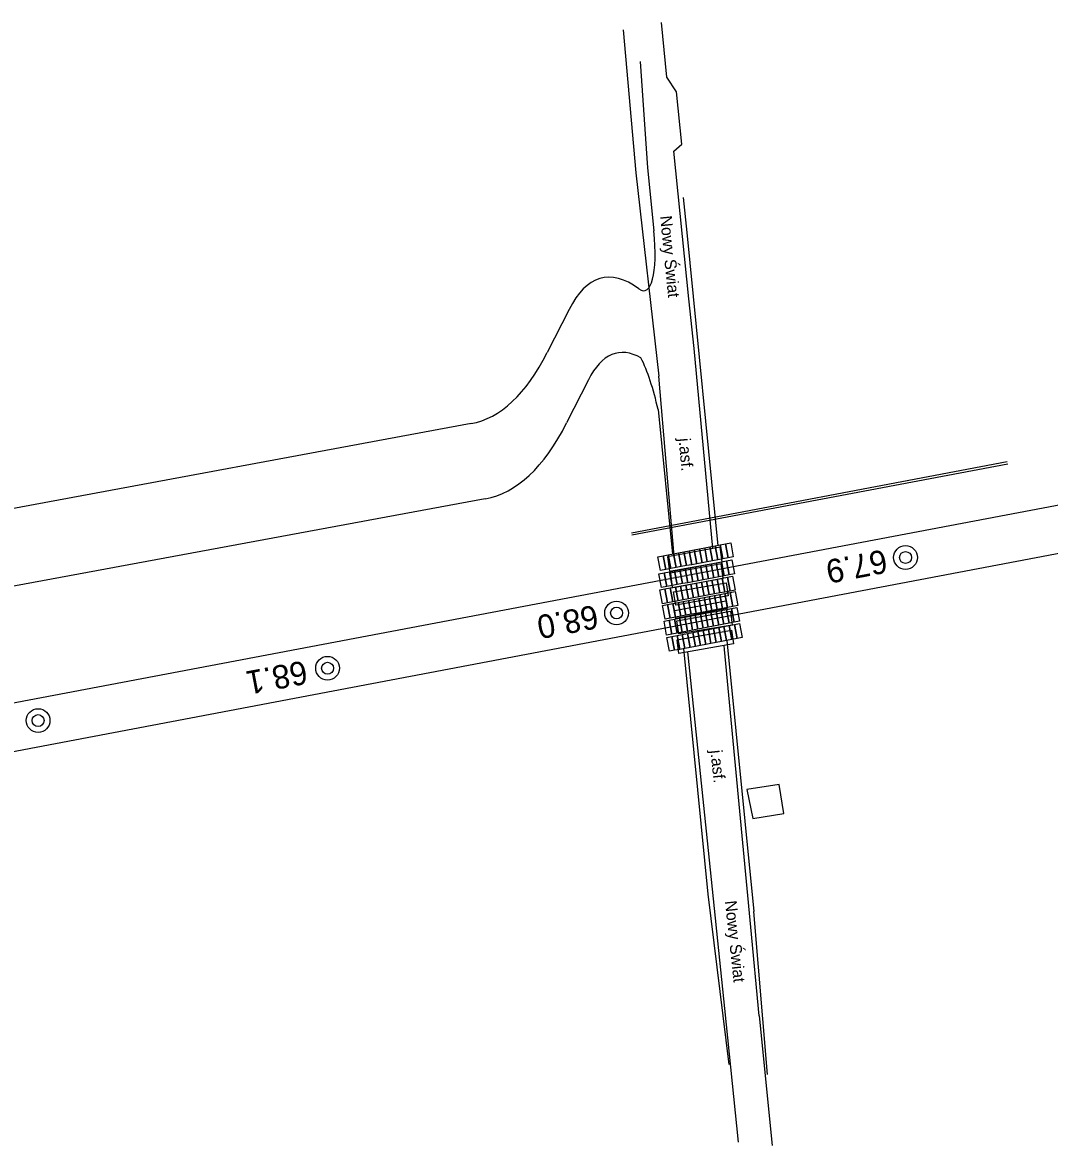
# Model space of a CAD drawing. Extents: x 6541740 to 6566395, y 5525066 to 5530361.
# Drawn here: x 6555554.3 to 6555641.5, y 5525816.3 to 5525911.7 of the extents above; entities that cross this region are included whole.
import ezdxf

# ---------------------------------------------------------------- set-up
doc = ezdxf.new("R2010")
doc.units = 0
for name, color, linetype in [('Domyślna', 7, 'Continuous'), ('ps_wymiarowanie', 7, 'Continuous'), ('TOR_PRZEK_P-komponent', 7, 'Continuous'), ('TOR_PS_OPIS_T-symbole geometrii', 7, 'Continuous'), ('TOR_PS_T-wypelnienia', 7, 'Continuous'), ('TOR_RAMKI-ramka+tabelka 1', 7, 'Continuous'), ('TOR_W-warstwa dodatkowa 2', 7, 'Continuous')]:
    doc.layers.add(name, color=color, linetype=linetype)

# ---------------------------------------------------------------- blocks, each defined once
blk = doc.blocks.new('4010_1')
at = {"layer": 'Domyślna'}
for radius in [0.75, 0.375]:
    blk.add_circle((0, 0), radius, dxfattribs=at)

msp = doc.modelspace()

# ---------------------------------------------------------------- linework, layer by layer
at = {"layer": 'ps_wymiarowanie'}
msp.add_lwpolyline([(6555615.817, 5525846.569), (6555616.342, 5525844.102), (6555618.975, 5525844.513), (6555618.567, 5525846.974)], close=True, dxfattribs=at)
at = {"layer": 'TOR_PRZEK_P-komponent'}
for p, q in [((6555661.881, 5525874.434), (6555417.835, 5525828.174)), ((6555662.569, 5525870.442), (6555511.666, 5525841.838))]:
    msp.add_line(p, q, dxfattribs=at)
at = {"layer": 'TOR_PS_OPIS_T-symbole geometrii'}
for p, q in [((6555606.773, 5525908.404), (6555607.395, 5525899.379)), ((6555607.395, 5525899.379), (6555607.929, 5525894.023)), ((6555610.407, 5525896.871), (6555610.719, 5525893.873)), ((6555610.719, 5525893.873), (6555613.372, 5525867.273)), ((6555600.722, 5525887.34), (6555598.873, 5525883.688)), ((6555602.367, 5525881.359), (6555600.517, 5525877.707)), ((6555608.288, 5525878.84), (6555609.514, 5525866.547)), ((6555592.391, 5525877.644), (6555510.496, 5525862.451)), ((6555593.6, 5525871.257), (6555511.705, 5525856.065)), ((6555610.446, 5525858.537), (6555612.527, 5525837.666)), ((6555614.129, 5525859.215), (6555616.426, 5525836.183)), ((6555612.527, 5525837.666), (6555614.286, 5525823.189)), ((6555617.577, 5525822.345), (6555616.426, 5525836.183))]:
    msp.add_line(p, q, dxfattribs=at)
for points in [[(6555611.802, 5525867.007), (6555612.028, 5525865.829), (6555611.585, 5525865.745), (6555611.36, 5525866.923)], [(6555612.245, 5525867.091), (6555612.47, 5525865.912), (6555612.028, 5525865.829), (6555611.802, 5525867.007)], [(6555612.687, 5525867.175), (6555612.912, 5525865.996), (6555612.47, 5525865.912), (6555612.245, 5525867.091)], [(6555613.129, 5525867.258), (6555613.354, 5525866.08), (6555612.912, 5525865.996), (6555612.687, 5525867.175)], [(6555613.571, 5525867.342), (6555613.796, 5525866.163), (6555613.354, 5525866.08), (6555613.129, 5525867.258)], [(6555614.013, 5525867.426), (6555614.238, 5525866.247), (6555613.796, 5525866.163), (6555613.571, 5525867.342)], [(6555614.455, 5525867.51), (6555614.68, 5525866.331), (6555614.238, 5525866.247), (6555614.013, 5525867.426)], [(6555608.707, 5525866.421), (6555608.933, 5525865.242), (6555608.49, 5525865.159), (6555608.265, 5525866.337)], [(6555609.15, 5525866.505), (6555609.375, 5525865.326), (6555608.933, 5525865.242), (6555608.707, 5525866.421)], [(6555609.592, 5525866.589), (6555609.817, 5525865.41), (6555609.375, 5525865.326), (6555609.15, 5525866.505)], [(6555610.034, 5525866.672), (6555610.259, 5525865.494), (6555609.817, 5525865.41), (6555609.592, 5525866.589)], [(6555610.476, 5525866.756), (6555610.701, 5525865.577), (6555610.259, 5525865.494), (6555610.034, 5525866.672)], [(6555610.918, 5525866.84), (6555611.143, 5525865.661), (6555610.701, 5525865.577), (6555610.476, 5525866.756)], [(6555611.36, 5525866.923), (6555611.585, 5525865.745), (6555611.143, 5525865.661), (6555610.918, 5525866.84)], [(6555614.554, 5525866.064), (6555614.779, 5525864.885), (6555614.337, 5525864.801), (6555614.112, 5525865.98)], [(6555609.691, 5525865.142), (6555609.916, 5525863.964), (6555609.474, 5525863.88), (6555609.249, 5525865.059)], [(6555610.133, 5525865.226), (6555610.358, 5525864.048), (6555609.916, 5525863.964), (6555609.691, 5525865.142)], [(6555610.575, 5525865.31), (6555610.8, 5525864.131), (6555610.358, 5525864.048), (6555610.133, 5525865.226)], [(6555611.017, 5525865.394), (6555611.242, 5525864.215), (6555610.8, 5525864.131), (6555610.575, 5525865.31)], [(6555611.459, 5525865.477), (6555611.684, 5525864.299), (6555611.242, 5525864.215), (6555611.017, 5525865.394)], [(6555611.901, 5525865.561), (6555612.127, 5525864.382), (6555611.684, 5525864.299), (6555611.459, 5525865.477)], [(6555612.344, 5525865.645), (6555612.569, 5525864.466), (6555612.127, 5525864.382), (6555611.901, 5525865.561)], [(6555612.786, 5525865.729), (6555613.011, 5525864.55), (6555612.569, 5525864.466), (6555612.344, 5525865.645)], [(6555613.228, 5525865.812), (6555613.453, 5525864.634), (6555613.011, 5525864.55), (6555612.786, 5525865.729)], [(6555613.67, 5525865.896), (6555613.895, 5525864.717), (6555613.453, 5525864.634), (6555613.228, 5525865.812)], [(6555614.112, 5525865.98), (6555614.337, 5525864.801), (6555613.895, 5525864.717), (6555613.67, 5525865.896)], [(6555608.807, 5525864.975), (6555609.032, 5525863.796), (6555608.589, 5525863.713), (6555608.364, 5525864.891)], [(6555609.249, 5525865.059), (6555609.474, 5525863.88), (6555609.032, 5525863.796), (6555608.807, 5525864.975)], [(6555611.967, 5525864.182), (6555612.192, 5525863.003), (6555611.75, 5525862.92), (6555611.525, 5525864.098)], [(6555612.409, 5525864.266), (6555612.635, 5525863.087), (6555612.192, 5525863.003), (6555611.967, 5525864.182)], [(6555612.852, 5525864.349), (6555613.077, 5525863.171), (6555612.635, 5525863.087), (6555612.409, 5525864.266)], [(6555613.294, 5525864.433), (6555613.519, 5525863.254), (6555613.077, 5525863.171), (6555612.852, 5525864.349)], [(6555613.736, 5525864.517), (6555613.961, 5525863.338), (6555613.519, 5525863.254), (6555613.294, 5525864.433)], [(6555614.178, 5525864.601), (6555614.403, 5525863.422), (6555613.961, 5525863.338), (6555613.736, 5525864.517)], [(6555614.62, 5525864.684), (6555614.845, 5525863.506), (6555614.403, 5525863.422), (6555614.178, 5525864.601)], [(6555608.872, 5525863.596), (6555609.097, 5525862.417), (6555608.655, 5525862.333), (6555608.43, 5525863.512)], [(6555609.314, 5525863.68), (6555609.54, 5525862.501), (6555609.097, 5525862.417), (6555608.872, 5525863.596)], [(6555609.757, 5525863.763), (6555609.982, 5525862.585), (6555609.54, 5525862.501), (6555609.314, 5525863.68)], [(6555610.199, 5525863.847), (6555610.424, 5525862.668), (6555609.982, 5525862.585), (6555609.757, 5525863.763)], [(6555610.641, 5525863.931), (6555610.866, 5525862.752), (6555610.424, 5525862.668), (6555610.199, 5525863.847)], [(6555611.083, 5525864.014), (6555611.308, 5525862.836), (6555610.866, 5525862.752), (6555610.641, 5525863.931)], [(6555611.525, 5525864.098), (6555611.75, 5525862.92), (6555611.308, 5525862.836), (6555611.083, 5525864.014)], [(6555613.964, 5525863.207), (6555614.189, 5525862.028), (6555613.747, 5525861.944), (6555613.522, 5525863.123)], [(6555614.406, 5525863.291), (6555614.631, 5525862.112), (6555614.189, 5525862.028), (6555613.964, 5525863.207)], [(6555614.848, 5525863.374), (6555615.073, 5525862.196), (6555614.631, 5525862.112), (6555614.406, 5525863.291)], [(6555609.1, 5525862.286), (6555609.325, 5525861.107), (6555608.883, 5525861.023), (6555608.658, 5525862.202)], [(6555609.542, 5525862.369), (6555609.767, 5525861.191), (6555609.325, 5525861.107), (6555609.1, 5525862.286)], [(6555609.984, 5525862.453), (6555610.21, 5525861.274), (6555609.767, 5525861.191), (6555609.542, 5525862.369)], [(6555610.427, 5525862.537), (6555610.652, 5525861.358), (6555610.21, 5525861.274), (6555609.984, 5525862.453)], [(6555610.869, 5525862.621), (6555611.094, 5525861.442), (6555610.652, 5525861.358), (6555610.427, 5525862.537)], [(6555611.311, 5525862.704), (6555611.536, 5525861.526), (6555611.094, 5525861.442), (6555610.869, 5525862.621)], [(6555611.753, 5525862.788), (6555611.978, 5525861.609), (6555611.536, 5525861.526), (6555611.311, 5525862.704)], [(6555612.195, 5525862.872), (6555612.42, 5525861.693), (6555611.978, 5525861.609), (6555611.753, 5525862.788)], [(6555612.637, 5525862.956), (6555612.862, 5525861.777), (6555612.42, 5525861.693), (6555612.195, 5525862.872)], [(6555613.079, 5525863.039), (6555613.305, 5525861.861), (6555612.862, 5525861.777), (6555612.637, 5525862.956)], [(6555613.522, 5525863.123), (6555613.747, 5525861.944), (6555613.305, 5525861.861), (6555613.079, 5525863.039)], [(6555610.999, 5525861.278), (6555611.224, 5525860.099), (6555610.782, 5525860.015), (6555610.557, 5525861.194)], [(6555611.441, 5525861.361), (6555611.666, 5525860.183), (6555611.224, 5525860.099), (6555610.999, 5525861.278)], [(6555611.884, 5525861.445), (6555612.109, 5525860.266), (6555611.666, 5525860.183), (6555611.441, 5525861.361)], [(6555612.326, 5525861.529), (6555612.551, 5525860.35), (6555612.109, 5525860.266), (6555611.884, 5525861.445)], [(6555612.768, 5525861.613), (6555612.993, 5525860.434), (6555612.551, 5525860.35), (6555612.326, 5525861.529)], [(6555613.21, 5525861.696), (6555613.435, 5525860.518), (6555612.993, 5525860.434), (6555612.768, 5525861.613)], [(6555613.652, 5525861.78), (6555613.877, 5525860.601), (6555613.435, 5525860.518), (6555613.21, 5525861.696)], [(6555614.094, 5525861.864), (6555614.319, 5525860.685), (6555613.877, 5525860.601), (6555613.652, 5525861.78)], [(6555614.536, 5525861.948), (6555614.761, 5525860.769), (6555614.319, 5525860.685), (6555614.094, 5525861.864)], [(6555614.978, 5525862.031), (6555615.204, 5525860.853), (6555614.761, 5525860.769), (6555614.536, 5525861.948)], [(6555609.231, 5525860.943), (6555609.456, 5525859.764), (6555609.014, 5525859.68), (6555608.789, 5525860.859)], [(6555609.673, 5525861.026), (6555609.898, 5525859.848), (6555609.456, 5525859.764), (6555609.231, 5525860.943)], [(6555610.115, 5525861.11), (6555610.34, 5525859.931), (6555609.898, 5525859.848), (6555609.673, 5525861.026)], [(6555610.557, 5525861.194), (6555610.782, 5525860.015), (6555610.34, 5525859.931), (6555610.115, 5525861.11)], [(6555613.441, 5525860.316), (6555613.666, 5525859.137), (6555613.224, 5525859.053), (6555612.999, 5525860.232)], [(6555613.883, 5525860.399), (6555614.108, 5525859.221), (6555613.666, 5525859.137), (6555613.441, 5525860.316)], [(6555614.325, 5525860.483), (6555614.55, 5525859.304), (6555614.108, 5525859.221), (6555613.883, 5525860.399)], [(6555614.767, 5525860.567), (6555614.992, 5525859.388), (6555614.55, 5525859.304), (6555614.325, 5525860.483)], [(6555615.21, 5525860.651), (6555615.435, 5525859.472), (6555614.992, 5525859.388), (6555614.767, 5525860.567)], [(6555609.462, 5525859.562), (6555609.687, 5525858.383), (6555609.245, 5525858.3), (6555609.02, 5525859.478)], [(6555609.904, 5525859.646), (6555610.129, 5525858.467), (6555609.687, 5525858.383), (6555609.462, 5525859.562)], [(6555610.346, 5525859.73), (6555610.571, 5525858.551), (6555610.129, 5525858.467), (6555609.904, 5525859.646)], [(6555610.788, 5525859.813), (6555611.013, 5525858.635), (6555610.571, 5525858.551), (6555610.346, 5525859.73)], [(6555611.23, 5525859.897), (6555611.455, 5525858.718), (6555611.013, 5525858.635), (6555610.788, 5525859.813)], [(6555611.672, 5525859.981), (6555611.897, 5525858.802), (6555611.455, 5525858.718), (6555611.23, 5525859.897)], [(6555612.115, 5525860.064), (6555612.34, 5525858.886), (6555611.897, 5525858.802), (6555611.672, 5525859.981)], [(6555612.557, 5525860.148), (6555612.782, 5525858.969), (6555612.34, 5525858.886), (6555612.115, 5525860.064)], [(6555612.999, 5525860.232), (6555613.224, 5525859.053), (6555612.782, 5525858.969), (6555612.557, 5525860.148)]]:
    msp.add_lwpolyline(points, close=True, dxfattribs=at)
for centre, major_axis, start_param, end_param in [((6555605.801, 5525896.073), (-1.35, 7.123), 2.87906, 4.373417), ((6555611.664, 5525847.546), (-8.055, 42.493), 6.020653, 6.597201), ((6555611.664, 5525847.546), (-6.844, 36.107), 6.075316, 6.597201), ((6555574.395, 5525972.706), (-18.018, 95.057), 3.140618, 3.455608), ((6555606.69, 5525877.613), (-1.35, 7.123), 4.837905, 5.571797), ((6555574.395, 5525972.706), (-19.229, 101.444), 3.140618, 3.455608)]:
    msp.add_ellipse(centre, major_axis=major_axis, ratio=0.25, start_param=start_param, end_param=end_param, dxfattribs=at)
at = {"layer": 'TOR_PS_T-wypelnienia'}
for p, q in [((6555605.315, 5525911.115), (6555606.385, 5525898.961)), ((6555609.037, 5525907.083), (6555608.566, 5525911.733)), ((6555609.841, 5525905.845), (6555609.037, 5525907.083)), ((6555610.294, 5525901.39), (6555609.841, 5525905.845)), ((6555609.623, 5525900.808), (6555610.294, 5525901.39)), ((6555610.891, 5525888.25), (6555609.623, 5525900.808)), ((6555606.385, 5525898.961), (6555608.345, 5525881.685)), ((6555613.957, 5525827.945), (6555612.481, 5525842.206)), ((6555616.889, 5525827.316), (6555616.163, 5525834.861)), ((6555615.12, 5525816.595), (6555613.957, 5525827.945)), ((6555616.889, 5525827.316), (6555617.99, 5525816.304))]:
    msp.add_line(p, q, dxfattribs=at)
for points in [[(6555612.928, 5525867.023), (6555611.343, 5525884.03), (6555610.891, 5525888.25)], [(6555609.661, 5525866.388), (6555608.345, 5525881.685)], [(6555609.884, 5525860.882), (6555614.444, 5525861.703), (6555614.575, 5525860.514), (6555610.057, 5525859.78), (6555609.884, 5525860.882)], [(6555616.163, 5525834.861), (6555613.94, 5525858.442), (6555613.911, 5525858.79)], [(6555612.481, 5525842.206), (6555610.848, 5525857.994), (6555610.82, 5525858.261)]]:
    msp.add_lwpolyline(points, dxfattribs=at)
for points in [[(6555613.575, 5525867.15), (6555609.097, 5525866.315), (6555609.268, 5525865.114), (6555613.729, 5525865.905)], [(6555613.657, 5525865.735), (6555609.349, 5525864.936), (6555609.494, 5525863.713), (6555613.807, 5525864.522)], [(6555609.601, 5525863.34), (6555614.078, 5525864.114), (6555614.227, 5525863.021), (6555609.795, 5525862.225)], [(6555609.709, 5525861.778), (6555614.053, 5525862.598), (6555614.152, 5525861.931), (6555609.793, 5525861.1)], [(6555609.918, 5525859.269), (6555614.523, 5525860.09), (6555614.683, 5525858.939), (6555610.061, 5525858.114)]]:
    msp.add_lwpolyline(points, close=True, dxfattribs=at)
at = {"layer": 'TOR_W-warstwa dodatkowa 2'}
for p, q in [((6555606.028, 5525868.38), (6555637.959, 5525874.433)), ((6555606.065, 5525868.184), (6555637.996, 5525874.236))]:
    msp.add_line(p, q, dxfattribs=at)

# ---------------------------------------------------------------- block references
at = {"layer": 'TOR_RAMKI-ramka+tabelka 1', "xscale": 1.345963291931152, "yscale": 1.345963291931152}
for p in [(6555629.311, 5525866.269), (6555604.759, 5525861.555), (6555580.203, 5525856.861), (6555555.605, 5525852.415)]:
    msp.add_blockref('4010_1', p, dxfattribs=at)

# ---------------------------------------------------------------- texts
at = {"layer": 'TOR_PS_T-wypelnienia'}
for s, rotation, p in [('Nowy Świat', 275.66644, (6555608.453, 5525895.271)), ('j.asf.', 275.02348, (6555610.031, 5525876.377)), ('j.asf.', 275.97049, (6555612.729, 5525849.867)), ('Nowy Świat', 276.17146, (6555613.96, 5525837.07))]:
    msp.add_text(s, height=1, rotation=rotation, dxfattribs=at).set_placement(p)
at = {"layer": 'TOR_RAMKI-ramka+tabelka 1'}
for s, p in [('67.9', (6555627.535, 5525866.976)), ('68.0', (6555602.983, 5525862.262)), ('68.1', (6555578.268, 5525857.538))]:
    msp.add_text(s, height=2, rotation=190.76907, dxfattribs=at).set_placement(p)

doc.saveas('drawing.dxf')
